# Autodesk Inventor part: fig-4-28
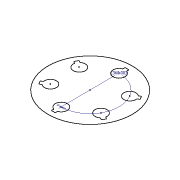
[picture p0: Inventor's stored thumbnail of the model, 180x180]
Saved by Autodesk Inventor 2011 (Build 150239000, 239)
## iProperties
Created: 2004-05
Part Number: fig-4-28
Document SubType Name: Modeling
Designer: CADCIM Technologies
Manufacturer: Standard
Standards Organization: Custom
Density: 1 g/cm^3
Author: CADCIM Technologies
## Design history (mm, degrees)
sketch "Sketch1"
  geometry: L1 (45.774, 51.065)-(45.774, 52.473); L2 (45.774, 52.473)-(43.425, 52.473); L3 (43.425, 52.473)-(43.425, 51.065); L4 (27.029, 41.48)-(25.81, 42.184); L5 (25.81, 42.184)-(24.635, 40.149); L6 (24.635, 40.149)-(25.855, 39.445); L7 (25.958, 20.454)-(24.739, 19.75); L8 (24.739, 19.75)-(25.914, 17.715); L9 (25.914, 17.715)-(27.133, 18.419); L10 (43.631, 9.012)-(43.631, 7.605); L11 (43.631, 7.605)-(45.981, 7.605); L12 (45.981, 7.605)-(45.981, 9.012); L13 (62.376, 18.598)-(63.595, 17.894); L14 (63.595, 17.894)-(64.77, 19.929); L15 (64.77, 19.929)-(63.551, 20.632); L16 (63.448, 39.624)-(64.667, 40.328); L17 (64.667, 40.328)-(63.492, 42.363); L18 (63.492, 42.363)-(62.273, 41.659); C1 r 25.482 at (44.703, 30.039); A1 r 3.618 centre (44.6, 47.644) between (43.425, 51.065) and (45.774, 51.065); A2 r 3.618 centre (29.405, 38.752) between (25.855, 39.445) and (27.029, 41.48); A3 r 3.618 centre (29.508, 21.147) between (27.133, 18.419) and (25.958, 20.454); A4 r 3.618 centre (44.806, 12.434) between (45.981, 9.012) and (43.631, 9.012); A5 r 3.618 centre (60.001, 21.326) between (63.551, 20.632) and (62.376, 18.598); A6 r 3.618 centre (59.897, 38.931) between (62.273, 41.659) and (63.448, 39.624)
  constraints: 36 end point, 12 point on circle, 7 centre point, 1 horizontal alignment, 1 parallel, 55 other
  dimensions: "d2" = 360 deg dimension on C1.centre A1.centre (derived)
